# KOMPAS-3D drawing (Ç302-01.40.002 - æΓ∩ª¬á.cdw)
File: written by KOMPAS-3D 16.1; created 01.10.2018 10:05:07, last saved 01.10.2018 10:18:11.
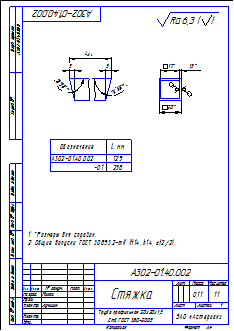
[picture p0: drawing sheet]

Sheet 1: A4, portrait

Title block, sheet 1: name: Стяжка; designation: А302-01.40.002; mass: 0,11; scale: 1:1; sheets: 1; organisation: ЗАО «Астерион»; sheet format: A4; stored path: \\192.168.87.28\Konstructor_doc\Мембранные насосы\Мембранный электропривод\А302-00.00.000 - ASTRA-302 (МЭ200)\3Д ПВХ\А302-01.40.002 - Стяжка.cdw; drawn by: Милов; technical control: Лучихин

Views: Вид 1, Вид:1, Проекционный вид 2
Referenced files in \\192.168.87.28\Konstructor_doc\Мембранные насосы\Мембранный электропривод\А302-00.00.000 - ASTRA-302 (МЭ200)\3Д ПВХ\Отработка\: Труба профильная 25х25х1,5-2.m3d
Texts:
  Труба профильная 20х20х1,5
  Ст3 ГОСТ 380-2005
  L, мм
  *Размеры для справок.
  Общие допуски ГОСТ 30893.2-mK (H14, h14,  t2/2).
  Ra 6,3
  Ra 6,3 ( )
Dimensions and other numbers on the sheet: 75 58'; 5; 20; 17; 1,5; -01; 258; 129; 1:1; 1; 0,11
